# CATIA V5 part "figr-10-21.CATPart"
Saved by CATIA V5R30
Part number: Part1
Bounding box of the stored display mesh (mm): x -60 to 60, y -90 to 70, z -46.082 to 16.155
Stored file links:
  D:\PROJECTS\CATIA V56R 2020\Resources\Parts File\c10_catia_v5_6r2020_prt\figr-10-21.CATPart
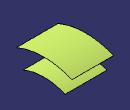
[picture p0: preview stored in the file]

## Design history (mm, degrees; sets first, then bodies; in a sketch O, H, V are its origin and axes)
Set1
  Sketch1 on yz-plane, origin (0, 0, 0), H (0, 1, 0), V (0, 0, 1)
    arc A1 centre (-10, -190) radius 206.1553 from (-90, 0) to (70, 0) cw
  Extrude1: Element1 Sketch1, Lim1 60, Lim2 60, Direction yz-plane
  Offset1: Offset Extrude1, Length 50
Body1 (main body)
